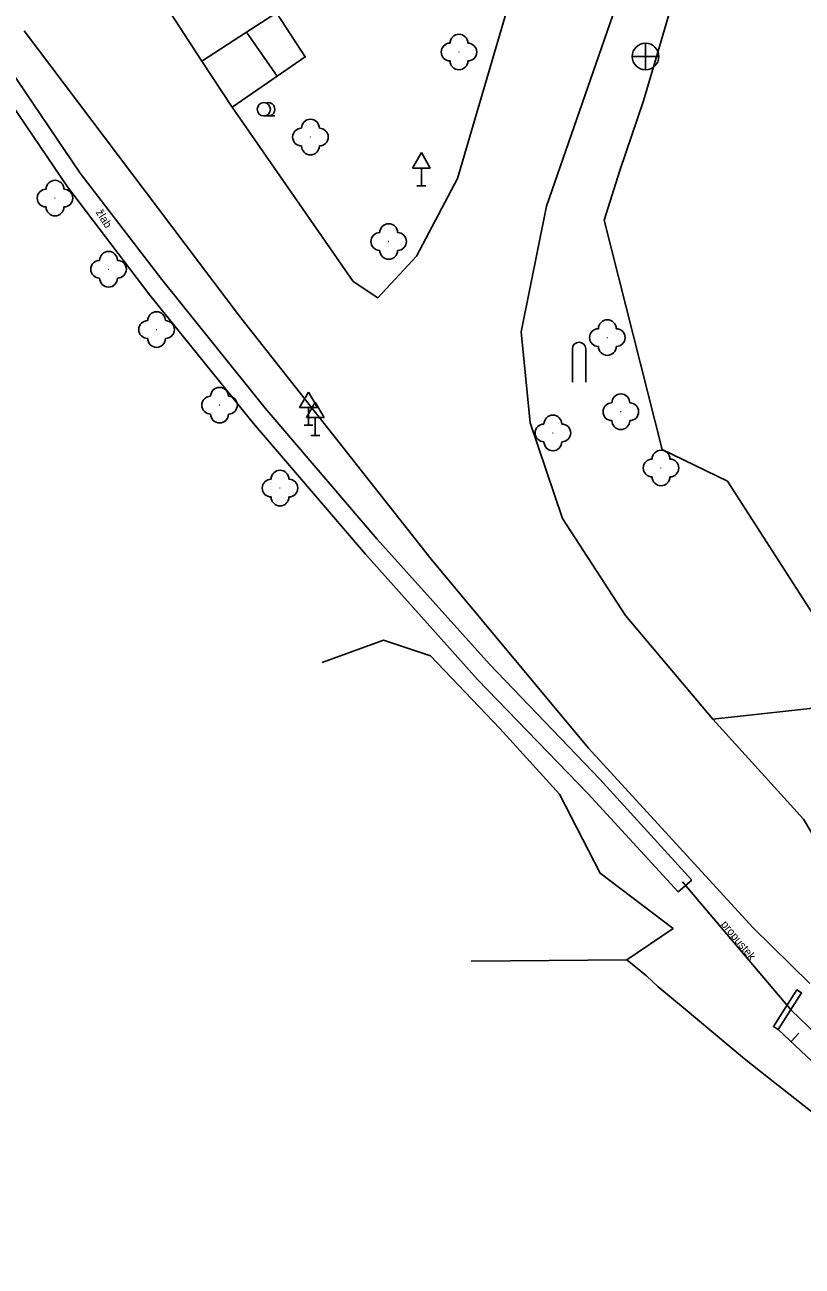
# Model space of a CAD drawing. Extents: x -747135 to -746147, y -1093269 to -1091735.
# Drawn here: x -747021.2 to -746977.5, y -1092250.8 to -1092181.1 of the extents above; entities that cross this region are included whole.
import ezdxf

# ---------------------------------------------------------------- set-up
doc = ezdxf.new("R2010")
doc.units = 0
for name, color, linetype in [('101', 7, 'Continuous'), ('1016', 7, 'Continuous'), ('1029', 7, 'Continuous'), ('105', 7, 'Continuous'), ('23700', 7, 'Continuous'), ('305', 7, 'Continuous'), ('306', 7, 'Continuous'), ('308', 7, 'Continuous'), ('316', 7, 'Continuous'), ('424', 7, 'Continuous'), ('803', 7, 'Continuous')]:
    doc.layers.add(name, color=color, linetype=linetype)

msp = doc.modelspace()

# ---------------------------------------------------------------- linework, layer by layer
at = {"layer": '101'}
for points in [[(-746963.97, -1092249.79), (-746969.17, -1092245), (-746978.08, -1092236.46)], [(-746978.84, -1092237.52), (-746969.32, -1092246.48)], [(-746978.112, -1092238.205), (-746977.672, -1092237.739)]]:
    msp.add_lwpolyline(points, dxfattribs=at)
at = {"layer": '1016'}
for points in [[(-746898.18, -1092134.6), (-746904.12, -1092139.99), (-746912.01, -1092144.83), (-746920.08, -1092149.17), (-746928.02, -1092152.73), (-746936.45, -1092155.39), (-746944.61, -1092157.47), (-746953.75, -1092158.71), (-746964.92, -1092159.66), (-746970.4, -1092160.58), (-746974.78, -1092162.27), (-746978.42, -1092164.61), (-746982.83, -1092169.13), (-746985.04, -1092172.77), (-746987.83, -1092179.63), (-746991.85, -1092191.24), (-746993.29, -1092198.31), (-746992.77, -1092203.42), (-746990.96, -1092208.81), (-746987.41, -1092214.26), (-746982.51, -1092220.09), (-746977.41, -1092225.71), (-746976.94, -1092226.48)], [(-747011.23, -1092183.09), (-747008.72, -1092181.47), (-747007.03, -1092180.37), (-747005.42, -1092182.85), (-747007.01, -1092183.94), (-747009.54, -1092185.67), (-747002.73, -1092195.47), (-747001.35, -1092196.39), (-746999.16, -1092194.05), (-746996.87, -1092189.68), (-746993.91, -1092179.58), (-746991.64, -1092174.26), (-746988.74, -1092168.88), (-746986.1, -1092164.49), (-746987.73, -1092161.59), (-746994.55, -1092161.35), (-746998.72, -1092160.89), (-747013.92, -1092161.88), (-747014.77, -1092163.04), (-747018.8, -1092163.16), (-747020.75, -1092164.97), (-747020.96, -1092168.13), (-747011.23, -1092183.09)], [(-746983.68, -1092229.13), (-746988.87, -1092223.46), (-746995.06, -1092216.98), (-747001.4, -1092209.94), (-747007.68, -1092202.6), (-747013.49, -1092195.37), (-747018.07, -1092189.38), (-747023.382, -1092181.582)], [(-746977.062, -1092234.946), (-746980.26, -1092231.79), (-746989.49, -1092221.72), (-746998.35, -1092211.08), (-747009.11, -1092197.43), (-747021.23, -1092181.39)], [(-747008.72, -1092181.47), (-747007.01, -1092183.94)], [(-747024.278, -1092182.079), (-747018.78, -1092190.16), (-747014.16, -1092196.24), (-747008.33, -1092203.47), (-747002.03, -1092210.81), (-746995.74, -1092217.86), (-746989.54, -1092224.26), (-746984.45, -1092229.78), (-746983.68, -1092229.13)], [(-747009.54, -1092185.67), (-747011.23, -1092183.09)], [(-746982.51, -1092220.09), (-746978.4, -1092219.64), (-746975.2, -1092219.27)], [(-746978.84, -1092237.52), (-746977.53, -1092235.46), (-746977.783, -1092235.298), (-746979.101, -1092237.352), (-746978.84, -1092237.52)]]:
    msp.add_lwpolyline(points, dxfattribs=at)
at = {"layer": '1029'}
msp.add_line((-747007.75, -1092186.175), (-747007.125, -1092186.175), dxfattribs=at)
msp.add_circle((-747007.75, -1092185.8), 0.375, dxfattribs=at)
msp.add_arc((-747007.5, -1092185.8), 0.375, 249.49437, 109.04743, dxfattribs=at)
at = {"layer": '23700'}
for points in [[(-746987.35, -1092233.61), (-746984.74, -1092231.85), (-746988.85, -1092228.74), (-746991.13, -1092224.29), (-746994.48, -1092220.6), (-746998.38, -1092216.53), (-747001.03, -1092215.64), (-747004.48, -1092216.9)], [(-746978.08, -1092236.46), (-746984.22, -1092229.22)]]:
    msp.add_lwpolyline(points, dxfattribs=at)
at = {"layer": '305'}
for points in [[(-746987.74, -1092189.24), (-746986.41, -1092185.33)], [(-746985.58, -1092235.13), (-746986.24, -1092234.51)], [(-746980.73, -1092239.17), (-746984.18, -1092236.28)]]:
    msp.add_lwpolyline(points, dxfattribs=at)
at = {"layer": '306'}
for p, q in [((-746998.89, -1092188.234), (-746999.39, -1092189.1)), ((-746998.89, -1092188.234), (-746998.39, -1092189.1)), ((-746999.39, -1092189.1), (-746998.39, -1092189.1)), ((-746998.89, -1092190.1), (-746998.89, -1092189.1)), ((-746999.14, -1092190.1), (-746998.64, -1092190.1)), ((-746990.405, -1092201.14), (-746990.405, -1092199.265)), ((-746989.655, -1092201.14), (-746989.655, -1092199.265)), ((-747005.24, -1092201.694), (-747005.74, -1092202.56)), ((-747005.24, -1092201.694), (-747004.74, -1092202.56)), ((-747005.74, -1092202.56), (-747004.74, -1092202.56)), ((-747004.86, -1092202.264), (-747005.36, -1092203.13)), ((-747005.24, -1092203.56), (-747005.24, -1092202.56)), ((-747004.86, -1092202.264), (-747004.36, -1092203.13)), ((-747005.36, -1092203.13), (-747004.36, -1092203.13)), ((-747004.86, -1092204.13), (-747004.86, -1092203.13)), ((-747005.49, -1092203.56), (-747004.99, -1092203.56)), ((-747005.11, -1092204.13), (-747004.61, -1092204.13))]:
    msp.add_line(p, q, dxfattribs=at)
msp.add_arc((-746990.03, -1092199.265), 0.375, 0, 179.99999, dxfattribs=at)
at = {"layer": '308'}
msp.add_lwpolyline([(-746964.91, -1092250.83), (-746969.32, -1092246.48), (-746970.3, -1092247.37), (-746979.38, -1092240.25)], dxfattribs=at)
at = {"layer": '316'}
for p, q in [((-746986.291, -1092183.578), (-746986.29, -1092182.083)), ((-746985.538, -1092182.836), (-746987.038, -1092182.831))]:
    msp.add_line(p, q, dxfattribs=at)
msp.add_circle((-746986.29, -1092182.83), 0.75, dxfattribs=at)
at = {"layer": '424'}
for centre in [(-746996.78, -1092182.58), (-747005.13, -1092187.36), (-747019.49, -1092190.79), (-747000.73, -1092193.23), (-747016.48, -1092194.79), (-747013.78, -1092198.18), (-746988.44, -1092198.63), (-747010.24, -1092202.43), (-746987.68, -1092202.8), (-746991.5, -1092203.99), (-746985.42, -1092205.96), (-747006.84, -1092207.09)]:
    msp.add_circle(centre, 0.0005, dxfattribs=at)
for centre, start, end in [((-746996.78, -1092182.08), 0, 179.99999), ((-746997.28, -1092182.58), 89.99999, 269.99999), ((-746996.28, -1092182.58), 270, 89.99999), ((-746996.78, -1092183.08), 179.99999, 359.99999), ((-747005.13, -1092186.86), 0, 179.99999), ((-747005.63, -1092187.36), 89.99999, 269.99999), ((-747004.63, -1092187.36), 270, 89.99999), ((-747005.13, -1092187.86), 179.99999, 359.99999), ((-747019.49, -1092190.29), 0, 179.99999), ((-747019.99, -1092190.79), 89.99999, 269.99999), ((-747018.99, -1092190.79), 270, 89.99999), ((-747019.49, -1092191.29), 179.99999, 359.99999), ((-747000.73, -1092192.73), 0, 179.99999), ((-747001.23, -1092193.23), 89.99999, 269.99999), ((-747000.23, -1092193.23), 270, 89.99999), ((-747000.73, -1092193.73), 179.99999, 359.99999), ((-747016.98, -1092194.79), 89.99999, 269.99999), ((-747016.48, -1092194.29), 0, 179.99999), ((-747015.98, -1092194.79), 270, 89.99999), ((-747016.48, -1092195.29), 179.99999, 359.99999), ((-747013.78, -1092197.68), 0, 179.99999), ((-747014.28, -1092198.18), 89.99999, 269.99999), ((-747013.28, -1092198.18), 270, 89.99999), ((-746988.44, -1092198.13), 0, 179.99999), ((-746988.94, -1092198.63), 89.99999, 269.99999), ((-746987.94, -1092198.63), 270, 89.99999), ((-747013.78, -1092198.68), 179.99999, 359.99999), ((-746988.44, -1092199.13), 179.99999, 359.99999), ((-747010.24, -1092201.93), 0, 179.99999), ((-747010.74, -1092202.43), 89.99999, 269.99999), ((-747009.74, -1092202.43), 270, 89.99999), ((-746987.68, -1092202.3), 0, 179.99999), ((-746988.18, -1092202.8), 89.99999, 269.99999), ((-746987.18, -1092202.8), 270, 89.99999), ((-747010.24, -1092202.93), 179.99999, 359.99999), ((-746992, -1092203.99), 89.99999, 269.99999), ((-746991.5, -1092203.49), 0, 179.99999), ((-746991, -1092203.99), 270, 89.99999), ((-746987.68, -1092203.3), 179.99999, 359.99999), ((-746991.5, -1092204.49), 179.99999, 359.99999), ((-746985.92, -1092205.96), 89.99999, 269.99999), ((-746985.42, -1092205.46), 0, 179.99999), ((-746984.92, -1092205.96), 270, 89.99999), ((-747006.84, -1092206.59), 0, 179.99999), ((-747007.34, -1092207.09), 89.99999, 269.99999), ((-747006.34, -1092207.09), 270, 89.99999), ((-746985.42, -1092206.46), 179.99999, 359.99999), ((-747006.84, -1092207.59), 179.99999, 359.99999)]:
    msp.add_arc(centre, 0.5, start, end, dxfattribs=at)
at = {"layer": '803'}
for points in [[(-746982.52, -1092172.14), (-746986.41, -1092185.33)], [(-746987.74, -1092189.24), (-746988.61, -1092192.03), (-746985.35, -1092204.92), (-746981.69, -1092206.7), (-746976.46, -1092214.83), (-746975.2, -1092219.27), (-746973.08, -1092218.66), (-746970.3, -1092217.12)], [(-746986.24, -1092234.51), (-746987.35, -1092233.61), (-746996.1, -1092233.69)], [(-746984.18, -1092236.28), (-746985.58, -1092235.13)], [(-746979.38, -1092240.25), (-746980.73, -1092239.17)]]:
    msp.add_lwpolyline(points, dxfattribs=at)

# ---------------------------------------------------------------- texts
at = {"layer": '105'}
for s, rotation, p in [('žlab', 301.93009, (-747017.219, -1092191.586)), ('propustek', 309.33801, (-746982.075, -1092231.626))]:
    msp.add_text(s, height=0.45, rotation=rotation, dxfattribs=at).set_placement(p)

doc.saveas('drawing.dxf')
